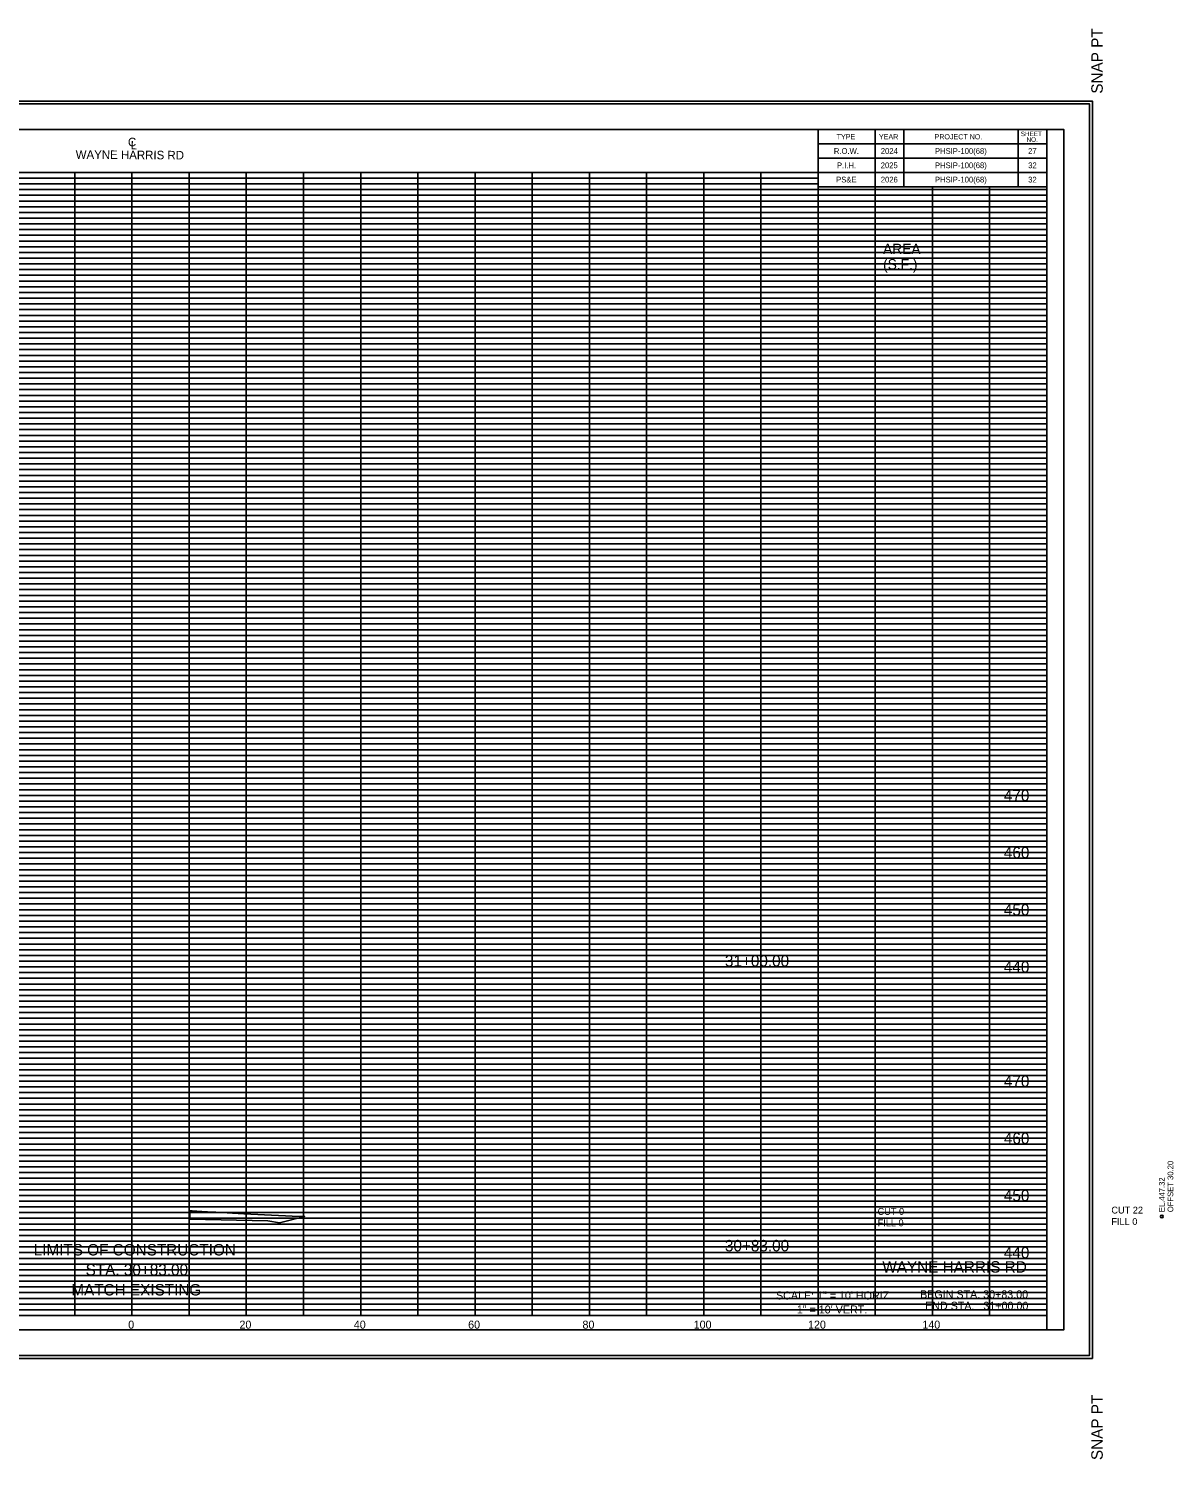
# Model space of a CAD drawing. Extents: x 986 to 1342, y 975 to 1485.
# Drawn here: x 1141.9 to 1342.2, y 1234.8 to 1485.2 of the extents above; entities that cross this region are included whole.
import ezdxf

# ---------------------------------------------------------------- set-up
doc = ezdxf.new("R2010")
doc.units = 0
for name, color, linetype in [('Default', 7, 'Continuous'), ('DESIGN - DRAINAGE - Special Ditch Width Text', 7, 'Continuous'), ('DESIGN - EARTHWORK - Shapes', 7, 'Continuous'), ('DESIGN - SCRATCH - User 1', 7, 'Continuous'), ('DESIGN - SHEET - Corner Text', 7, 'Continuous'), ('DESIGN - SHEET - Light Grid', 7, 'Continuous'), ('DESIGN - SHEET - Linework', 7, 'Continuous'), ('DESIGN - SHEET - Plot Shape', 7, 'Continuous'), ('DESIGN - TYPICAL - Slope Tie Point', 7, 'Continuous'), ('DESIGN - TYPICAL - Slope Tie Text', 7, 'Continuous'), ('DESIGN - TYPICAL - Text', 7, 'Continuous')]:
    doc.layers.add(name, color=color, linetype=linetype)

msp = doc.modelspace()

# ---------------------------------------------------------------- linework, layer by layer
at = {"layer": 'DESIGN - EARTHWORK - Shapes'}
msp.add_lwpolyline([(1170.11, 1276.83), (1170.11, 1278.33), (1170.34, 1278.32), (1170.5, 1278.31), (1172.19, 1278.2), (1173.2, 1278.14), (1174.17, 1278.08), (1174.64, 1278.05), (1179.56, 1277.77), (1185.62, 1277.48), (1189.23, 1277.32), (1190.2, 1277.32), (1185.79, 1276.22), (1183.79, 1276.56)], close=True, dxfattribs=at)
at = {"layer": 'DESIGN - SCRATCH - User 1'}
for p, q in [((1285, 1463.75), (1285, 1463.75)), ((1292.5, 1463.75), (1292.5, 1463.75)), ((1305, 1463.75), (1305, 1463.75)), ((1317.5, 1463.75), (1317.5, 1463.75)), ((1285, 1461.25), (1285, 1461.25)), ((1292.5, 1461.25), (1292.5, 1461.25)), ((1305, 1461.25), (1305, 1461.25)), ((1317.5, 1461.25), (1317.5, 1461.25))]:
    msp.add_line(p, q, dxfattribs=at)
at = {"layer": 'DESIGN - SHEET - Light Grid'}
for p, q in [((1000, 1459), (1280, 1459)), ((1000, 1458), (1280, 1458)), ((1000, 1457), (1320, 1457)), ((1000, 1456), (1320, 1456)), ((1000, 1455), (1320, 1455)), ((1000, 1454), (1320, 1454)), ((1000, 1453), (1320, 1453)), ((1000, 1452), (1320, 1452)), ((1000, 1451), (1320, 1451)), ((1000, 1449), (1320, 1449)), ((1000, 1448), (1320, 1448)), ((1000, 1447), (1320, 1447)), ((1000, 1446), (1320, 1446)), ((1000, 1445), (1320, 1445)), ((1000, 1444), (1320, 1444)), ((1000, 1443), (1320, 1443)), ((1000, 1442), (1320, 1442)), ((1000, 1441), (1320, 1441)), ((1000, 1439), (1320, 1439)), ((1000, 1438), (1320, 1438)), ((1000, 1437), (1320, 1437)), ((1000, 1436), (1320, 1436)), ((1000, 1435), (1320, 1435)), ((1000, 1434), (1320, 1434)), ((1000, 1433), (1320, 1433)), ((1000, 1432), (1320, 1432)), ((1000, 1431), (1320, 1431)), ((1000, 1429), (1320, 1429)), ((1000, 1428), (1320, 1428)), ((1000, 1427), (1320, 1427)), ((1000, 1426), (1320, 1426)), ((1000, 1425), (1320, 1425)), ((1000, 1424), (1320, 1424)), ((1000, 1423), (1320, 1423)), ((1000, 1422), (1320, 1422)), ((1000, 1421), (1320, 1421)), ((1000, 1419), (1320, 1419)), ((1000, 1418), (1320, 1418)), ((1000, 1417), (1320, 1417)), ((1000, 1416), (1320, 1416)), ((1000, 1415), (1320, 1415)), ((1000, 1414), (1320, 1414)), ((1000, 1413), (1320, 1413)), ((1000, 1412), (1320, 1412)), ((1000, 1411), (1320, 1411)), ((1000, 1409), (1320, 1409)), ((1000, 1408), (1320, 1408)), ((1000, 1407), (1320, 1407)), ((1000, 1406), (1320, 1406)), ((1000, 1405), (1320, 1405)), ((1000, 1404), (1320, 1404)), ((1000, 1403), (1320, 1403)), ((1000, 1402), (1320, 1402)), ((1000, 1401), (1320, 1401)), ((1000, 1399), (1320, 1399)), ((1000, 1398), (1320, 1398)), ((1000, 1397), (1320, 1397)), ((1000, 1396), (1320, 1396)), ((1000, 1395), (1320, 1395)), ((1000, 1394), (1320, 1394)), ((1000, 1393), (1320, 1393)), ((1000, 1392), (1320, 1392)), ((1000, 1391), (1320, 1391)), ((1000, 1389), (1320, 1389)), ((1000, 1388), (1320, 1388)), ((1000, 1387), (1320, 1387)), ((1000, 1386), (1320, 1386)), ((1000, 1385), (1320, 1385)), ((1000, 1384), (1320, 1384)), ((1000, 1383), (1320, 1383)), ((1000, 1382), (1320, 1382)), ((1000, 1381), (1320, 1381)), ((1000, 1379), (1320, 1379)), ((1000, 1378), (1320, 1378)), ((1000, 1377), (1320, 1377)), ((1000, 1376), (1320, 1376)), ((1000, 1375), (1320, 1375)), ((1000, 1374), (1320, 1374)), ((1000, 1373), (1320, 1373)), ((1000, 1372), (1320, 1372)), ((1000, 1371), (1320, 1371)), ((1000, 1369), (1320, 1369)), ((1000, 1368), (1320, 1368)), ((1000, 1367), (1320, 1367)), ((1000, 1366), (1320, 1366)), ((1000, 1365), (1320, 1365)), ((1000, 1364), (1320, 1364)), ((1000, 1363), (1320, 1363)), ((1000, 1362), (1320, 1362)), ((1000, 1361), (1320, 1361)), ((1000, 1359), (1320, 1359)), ((1000, 1358), (1320, 1358)), ((1000, 1357), (1320, 1357)), ((1000, 1356), (1320, 1356)), ((1000, 1355), (1320, 1355)), ((1000, 1354), (1320, 1354)), ((1000, 1353), (1320, 1353)), ((1000, 1352), (1320, 1352)), ((1000, 1351), (1320, 1351)), ((1000, 1349), (1320, 1349)), ((1000, 1348), (1320, 1348)), ((1000, 1347), (1320, 1347)), ((1000, 1346), (1320, 1346)), ((1000, 1345), (1320, 1345)), ((1000, 1344), (1320, 1344)), ((1000, 1343), (1320, 1343)), ((1000, 1342), (1320, 1342)), ((1000, 1341), (1320, 1341)), ((1000, 1339), (1320, 1339)), ((1000, 1338), (1320, 1338)), ((1000, 1337), (1320, 1337)), ((1000, 1336), (1320, 1336)), ((1000, 1335), (1320, 1335)), ((1000, 1334), (1320, 1334)), ((1000, 1333), (1320, 1333)), ((1000, 1332), (1320, 1332)), ((1000, 1331), (1320, 1331)), ((1000, 1329), (1320, 1329)), ((1000, 1328), (1320, 1328)), ((1000, 1327), (1320, 1327)), ((1000, 1326), (1320, 1326)), ((1000, 1325), (1320, 1325)), ((1000, 1324), (1320, 1324)), ((1000, 1323), (1320, 1323)), ((1000, 1322), (1320, 1322)), ((1000, 1321), (1320, 1321)), ((1000, 1319), (1320, 1319)), ((1000, 1318), (1320, 1318)), ((1000, 1317), (1320, 1317)), ((1000, 1316), (1320, 1316)), ((1000, 1315), (1320, 1315)), ((1000, 1314), (1320, 1314)), ((1000, 1313), (1320, 1313)), ((1000, 1312), (1320, 1312)), ((1000, 1311), (1320, 1311)), ((1000, 1309), (1320, 1309)), ((1000, 1308), (1320, 1308)), ((1000, 1307), (1320, 1307)), ((1000, 1306), (1320, 1306)), ((1000, 1305), (1320, 1305)), ((1000, 1304), (1320, 1304)), ((1000, 1303), (1320, 1303)), ((1000, 1302), (1320, 1302)), ((1000, 1301), (1320, 1301)), ((1000, 1299), (1320, 1299)), ((1000, 1298), (1320, 1298)), ((1000, 1297), (1320, 1297)), ((1000, 1296), (1320, 1296)), ((1000, 1295), (1320, 1295)), ((1000, 1294), (1320, 1294)), ((1000, 1293), (1320, 1293)), ((1000, 1292), (1320, 1292)), ((1000, 1291), (1320, 1291)), ((1000, 1289), (1320, 1289)), ((1000, 1288), (1320, 1288)), ((1000, 1287), (1320, 1287)), ((1000, 1286), (1320, 1286)), ((1000, 1285), (1320, 1285)), ((1000, 1284), (1320, 1284)), ((1000, 1283), (1320, 1283)), ((1000, 1282), (1320, 1282)), ((1000, 1281), (1320, 1281)), ((1000, 1279), (1320, 1279)), ((1000, 1278), (1320, 1278)), ((1000, 1277), (1320, 1277)), ((1000, 1276), (1320, 1276)), ((1000, 1275), (1320, 1275)), ((1000, 1274), (1320, 1274)), ((1000, 1273), (1320, 1273)), ((1000, 1272), (1320, 1272)), ((1000, 1271), (1320, 1271)), ((1000, 1269), (1320, 1269)), ((1000, 1268), (1320, 1268)), ((1000, 1267), (1320, 1267)), ((1000, 1266), (1320, 1266)), ((1000, 1265), (1320, 1265)), ((1000, 1264), (1320, 1264)), ((1000, 1263), (1320, 1263)), ((1000, 1262), (1320, 1262)), ((1000, 1261), (1320, 1261))]:
    msp.add_line(p, q, dxfattribs=at)
at = {"layer": 'DESIGN - SHEET - Linework'}
for p, q in [((1320, 1467.5), (1280, 1467.5)), ((1280, 1460), (1280, 1467.5)), ((1290, 1460), (1290, 1467.5)), ((1295, 1457.5), (1295, 1467.5)), ((1315, 1457.5), (1315, 1467.5)), ((1320, 1460), (1320, 1467.5)), ((1320, 1465), (1280, 1465)), ((1320, 1462.5), (1280, 1462.5)), ((1000, 1460), (1320, 1460)), ((1150, 1260), (1150, 1460)), ((1160, 1260), (1160, 1460)), ((1170, 1260), (1170, 1460)), ((1180, 1260), (1180, 1460)), ((1190, 1260), (1190, 1460)), ((1200, 1260), (1200, 1460)), ((1210, 1260), (1210, 1460)), ((1220, 1260), (1220, 1460)), ((1230, 1260), (1230, 1460)), ((1240, 1260), (1240, 1460)), ((1250, 1260), (1250, 1460)), ((1260, 1260), (1260, 1460)), ((1270, 1260), (1270, 1460)), ((1280, 1260), (1280, 1460)), ((1290, 1260), (1290, 1460)), ((1320, 1457.5), (1280, 1457.5)), ((1300, 1260), (1300, 1457.5)), ((1310, 1260), (1310, 1457.5)), ((1000, 1450), (1320, 1450)), ((1000, 1440), (1320, 1440)), ((1000, 1430), (1320, 1430)), ((1000, 1420), (1320, 1420)), ((1000, 1410), (1320, 1410)), ((1000, 1400), (1320, 1400)), ((1000, 1390), (1320, 1390)), ((1000, 1380), (1320, 1380)), ((1000, 1370), (1320, 1370)), ((1000, 1360), (1320, 1360)), ((1000, 1350), (1320, 1350)), ((1000, 1340), (1320, 1340)), ((1000, 1330), (1320, 1330)), ((1000, 1320), (1320, 1320)), ((1000, 1310), (1320, 1310)), ((1000, 1300), (1320, 1300)), ((1000, 1290), (1320, 1290)), ((1000, 1280), (1320, 1280)), ((1000, 1270), (1320, 1270)), ((1000, 1260), (1320, 1260))]:
    msp.add_line(p, q, dxfattribs=at)
for points in [[(988, 1472.5), (1328, 1472.5), (1328, 1252.5), (988, 1252.5)], [(1000, 1467.5), (1320, 1467.5), (1320, 1257.5), (1000, 1257.5)]]:
    msp.add_lwpolyline(points, close=True, dxfattribs=at)
at = {"layer": 'DESIGN - SHEET - Plot Shape'}
for points in [[(988.5, 1253), (1327.5, 1253), (1327.5, 1472), (988.5, 1472)], [(993, 1257.5), (1323, 1257.5), (1323, 1467.5), (993, 1467.5)]]:
    msp.add_lwpolyline(points, close=True, dxfattribs=at)
at = {"layer": 'DESIGN - TYPICAL - Slope Tie Point'}
msp.add_circle((1340.14, 1277.32), 0.25, dxfattribs=at)

# ---------------------------------------------------------------- texts
at = {"layer": 'Default'}
for s, height, p in [('     470     ', 2, (1308.79, 1350)), ('     460     ', 2, (1308.79, 1340)), ('     450     ', 2, (1308.79, 1330)), ('     31+00.00     ', 2, (1260, 1321.05)), ('     440     ', 2, (1308.79, 1320)), ('     470     ', 2, (1308.79, 1300)), ('     460     ', 2, (1308.79, 1290)), ('     450     ', 2, (1308.79, 1280)), ('     30+83.00     ', 2, (1260, 1271.22)), ('     440     ', 2, (1308.79, 1270)), ('     0     ', 1.4, (1156.74, 1257.7)), ('     0     ', 1.4, (1156.74, 1257.7)), ('     20     ', 1.4, (1176.2, 1257.7)), ('     40     ', 1.4, (1196.2, 1257.7)), ('     60     ', 1.4, (1216.2, 1257.7)), ('     80     ', 1.4, (1236.2, 1257.7)), ('     100     ', 1.4, (1255.65, 1257.7)), ('     120     ', 1.4, (1275.65, 1257.7)), ('     140     ', 1.4, (1295.65, 1257.7))]:
    msp.add_text(s, height=height, dxfattribs=at).set_placement(p)
at = {"layer": 'DESIGN - DRAINAGE - Special Ditch Width Text'}
for s, p in [('C', (1159.29, 1464.58)), ('L', (1159.79, 1464.03)), ('WAYNE HARRIS RD', (1150.15, 1462.38))]:
    msp.add_text(s, height=1.5, rotation=359.6675, dxfattribs=at).set_placement(p)
at = {"layer": 'DESIGN - SHEET - Corner Text'}
for s, p in [('  SNAP PT', (1329.8, 1472.3)), ('SNAP PT  ', (1329.8, 1234.7))]:
    msp.add_text(s, height=2, rotation=90, dxfattribs=at).set_placement(p)
for s, height, p in [('R.O.W.', 1, (1282.77, 1463.25)), ('2024', 1, (1290.98, 1463.25)), ('PHSIP-100(68)', 1, (1300.45, 1463.25)), ('27', 1, (1316.75, 1463.25)), ('P.I.H.', 1, (1283.31, 1460.75)), ('2025', 1, (1290.97, 1460.75)), ('PHSIP-100(68)', 1, (1300.45, 1460.75)), ('32', 1, (1316.76, 1460.75)), ('PS&E', 1, (1283.17, 1458.25)), ('2026', 1, (1290.98, 1458.25)), ('PHSIP-100(68)', 1, (1300.45, 1458.25)), ('32', 1, (1316.76, 1458.25)), ('WAYNE HARRIS RD', 2, (1291.25, 1267.5)), ('BEGIN STA. 30+83.00', 1.4, (1297.86, 1263)), ('SCALE: 1" = 10\' HORIZ.', 1.4, (1272.65, 1262.8)), ('       1" = 10\' VERT.   ', 1.4, (1272.65, 1260.35)), ('END STA.   31+00.00', 1.4, (1298.73, 1261))]:
    msp.add_text(s, height=height, dxfattribs=at).set_placement(p)
at = {"layer": 'DESIGN - SHEET - Light Grid'}
for s, height, p in [('SHEET', 0.8, (1315.47, 1466.35)), ('TYPE', 0.9, (1283.26, 1465.8)), ('YEAR', 0.9, (1290.66, 1465.8)), ('PROJECT NO.', 0.9, (1300.38, 1465.8)), ('NO.', 0.8, (1316.47, 1465.35))]:
    msp.add_text(s, height=height, dxfattribs=at).set_placement(p)
at = {"layer": 'DESIGN - TYPICAL - Slope Tie Text'}
for s, p in [('OFFSET 30.20', (1342.14, 1278.07)), ('EL.447.32', (1340.64, 1278.07))]:
    msp.add_text(s, height=1, rotation=90, dxfattribs=at).set_placement(p)
at = {"layer": 'DESIGN - TYPICAL - Text'}
for s, height, p in [('AREA ', 1.8, (1291.38, 1445.73)), ('(S.F.)', 1.8, (1291.38, 1443.03)), ('CUT 0', 1.2, (1290.42, 1277.61)), ('FILL 0', 1.2, (1290.42, 1275.61)), ('CUT 22', 1.2, (1331.31, 1277.84)), ('FILL 0', 1.2, (1331.31, 1275.84)), ('LIMITS OF CONSTRUCTION', 2, (1142.81, 1270.5)), ('STA. 30+83.00', 2, (1151.89, 1267)), ('MATCH EXISTING', 2, (1149.39, 1263.5))]:
    msp.add_text(s, height=height, dxfattribs=at).set_placement(p)

doc.saveas('drawing.dxf')
